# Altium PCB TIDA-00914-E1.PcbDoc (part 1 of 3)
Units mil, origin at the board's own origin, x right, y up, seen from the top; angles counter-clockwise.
Board outline 6575 x 7007.88 mil, 4 copper layers (Top Layer, GND, PWR, Bottom Layer), stack 79.834 mil thick; 302 components, 122 nets, 688 pads, 184 vias.
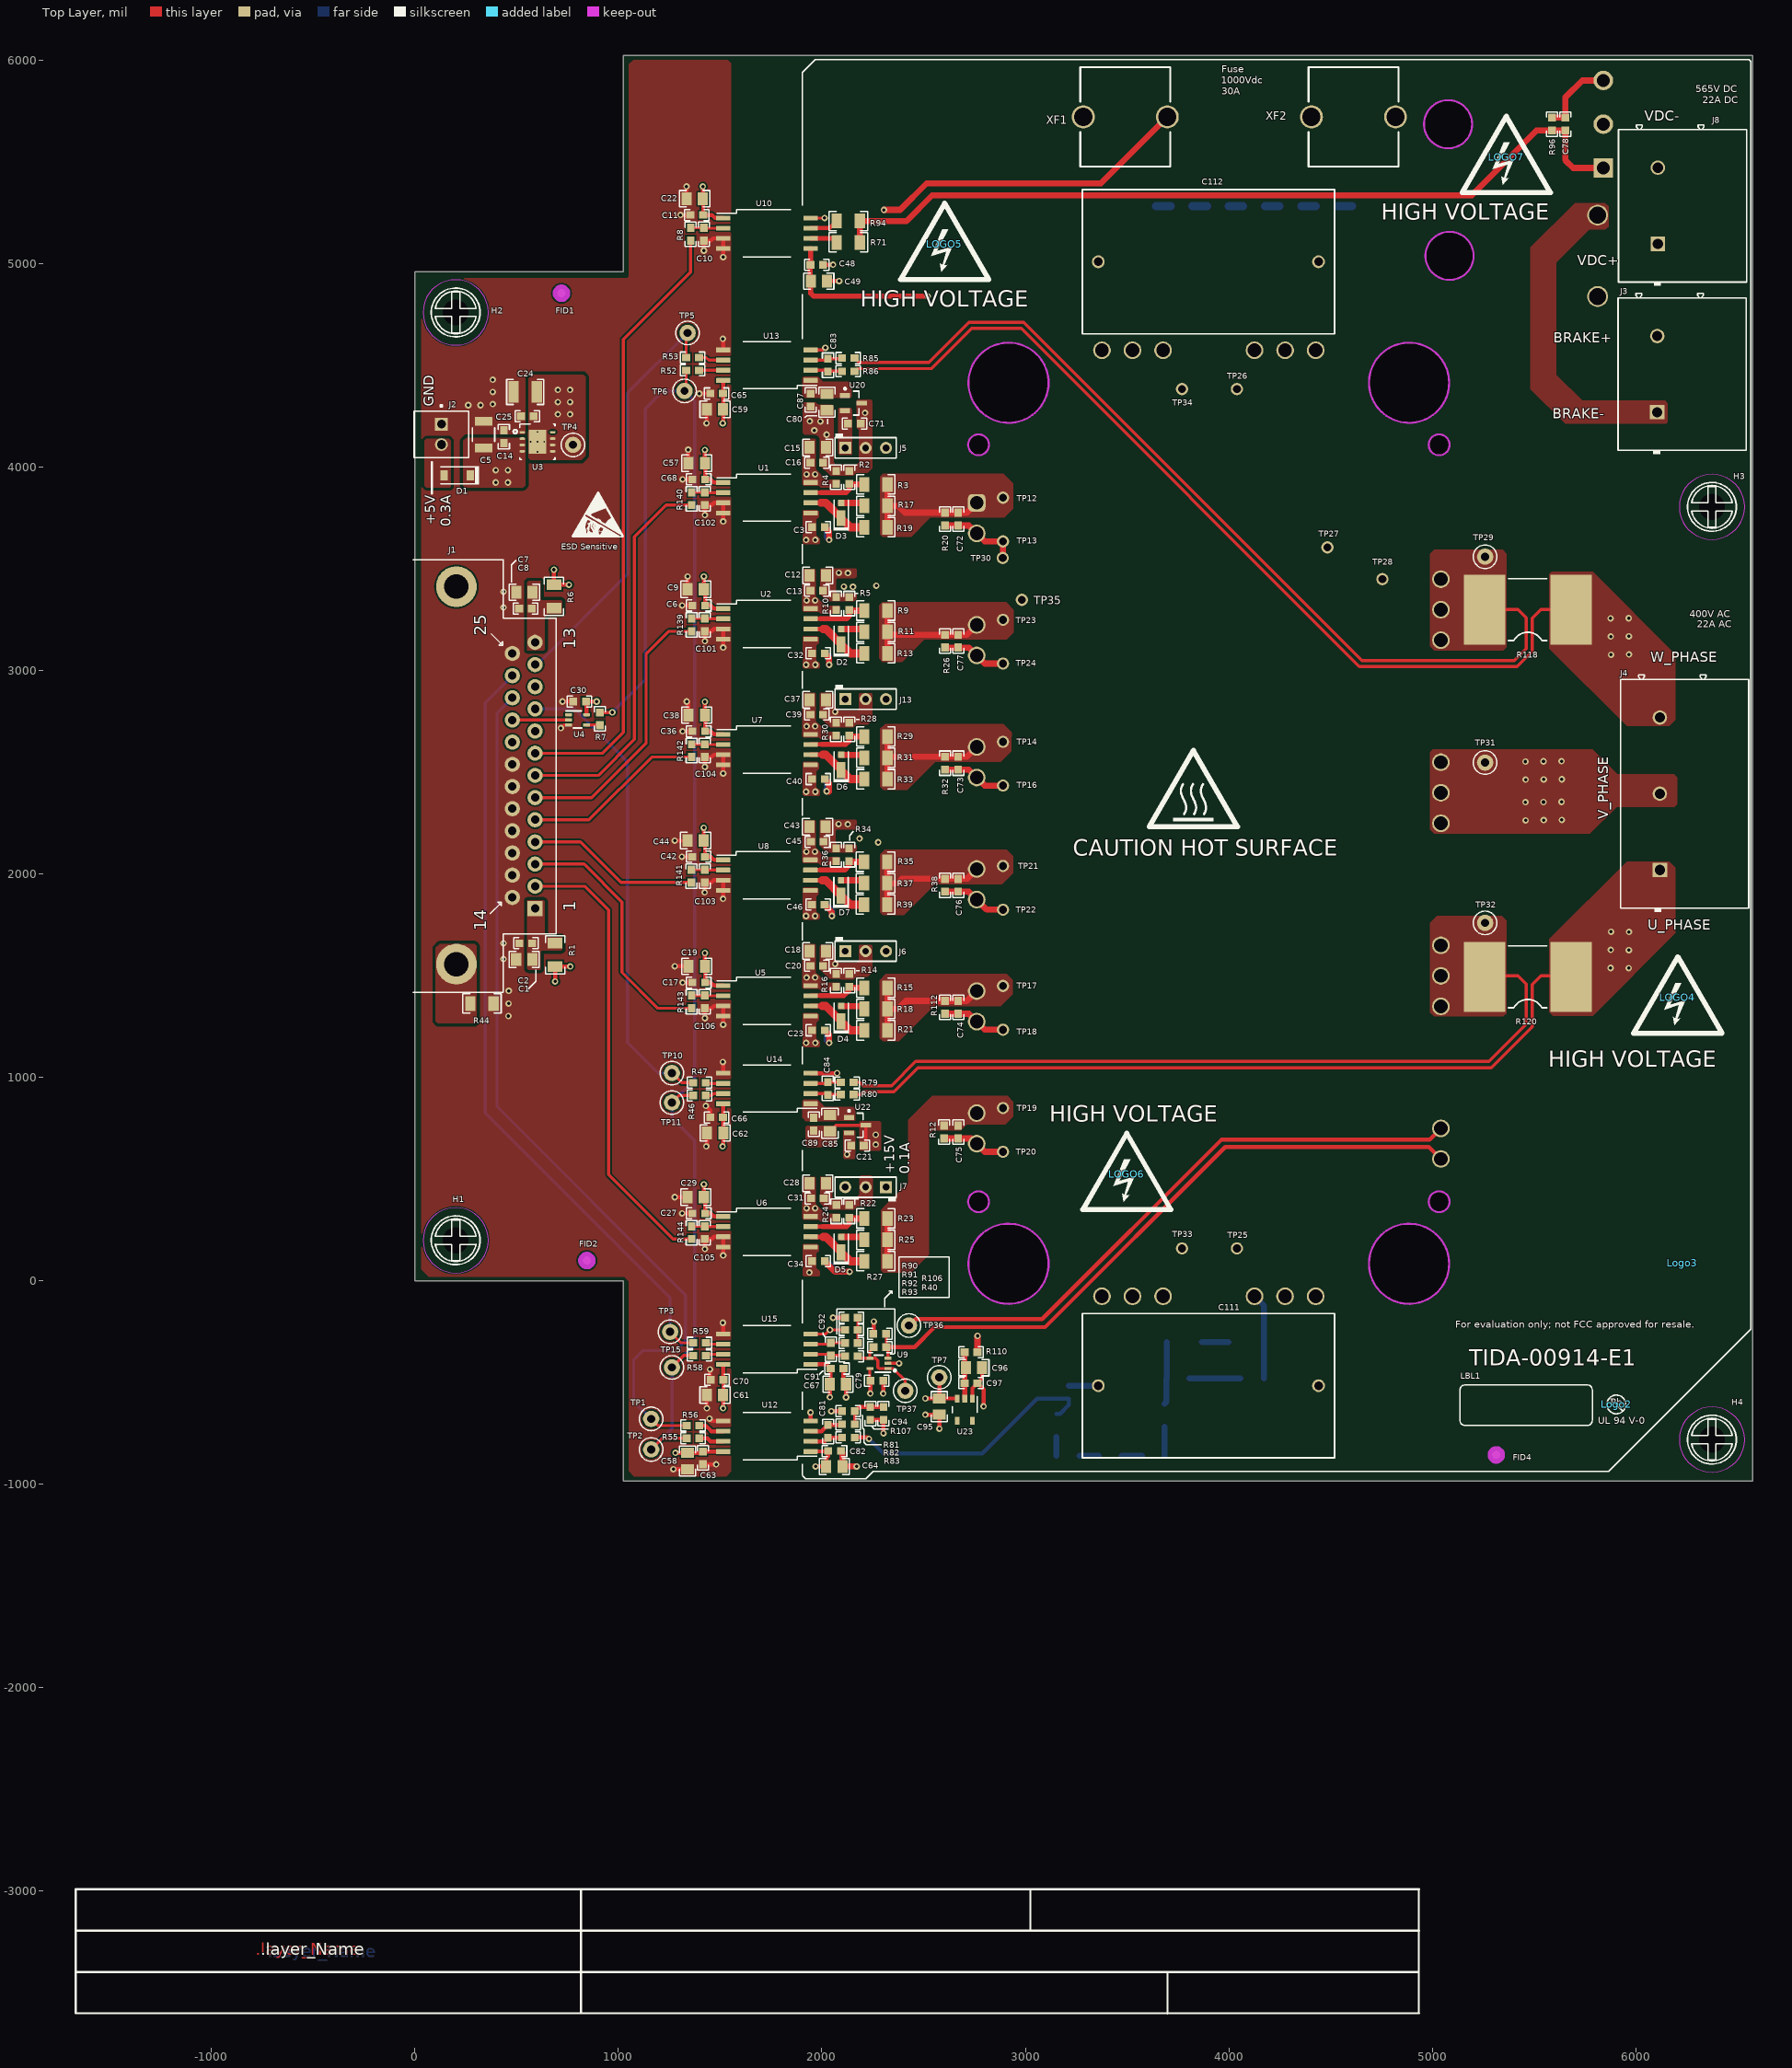
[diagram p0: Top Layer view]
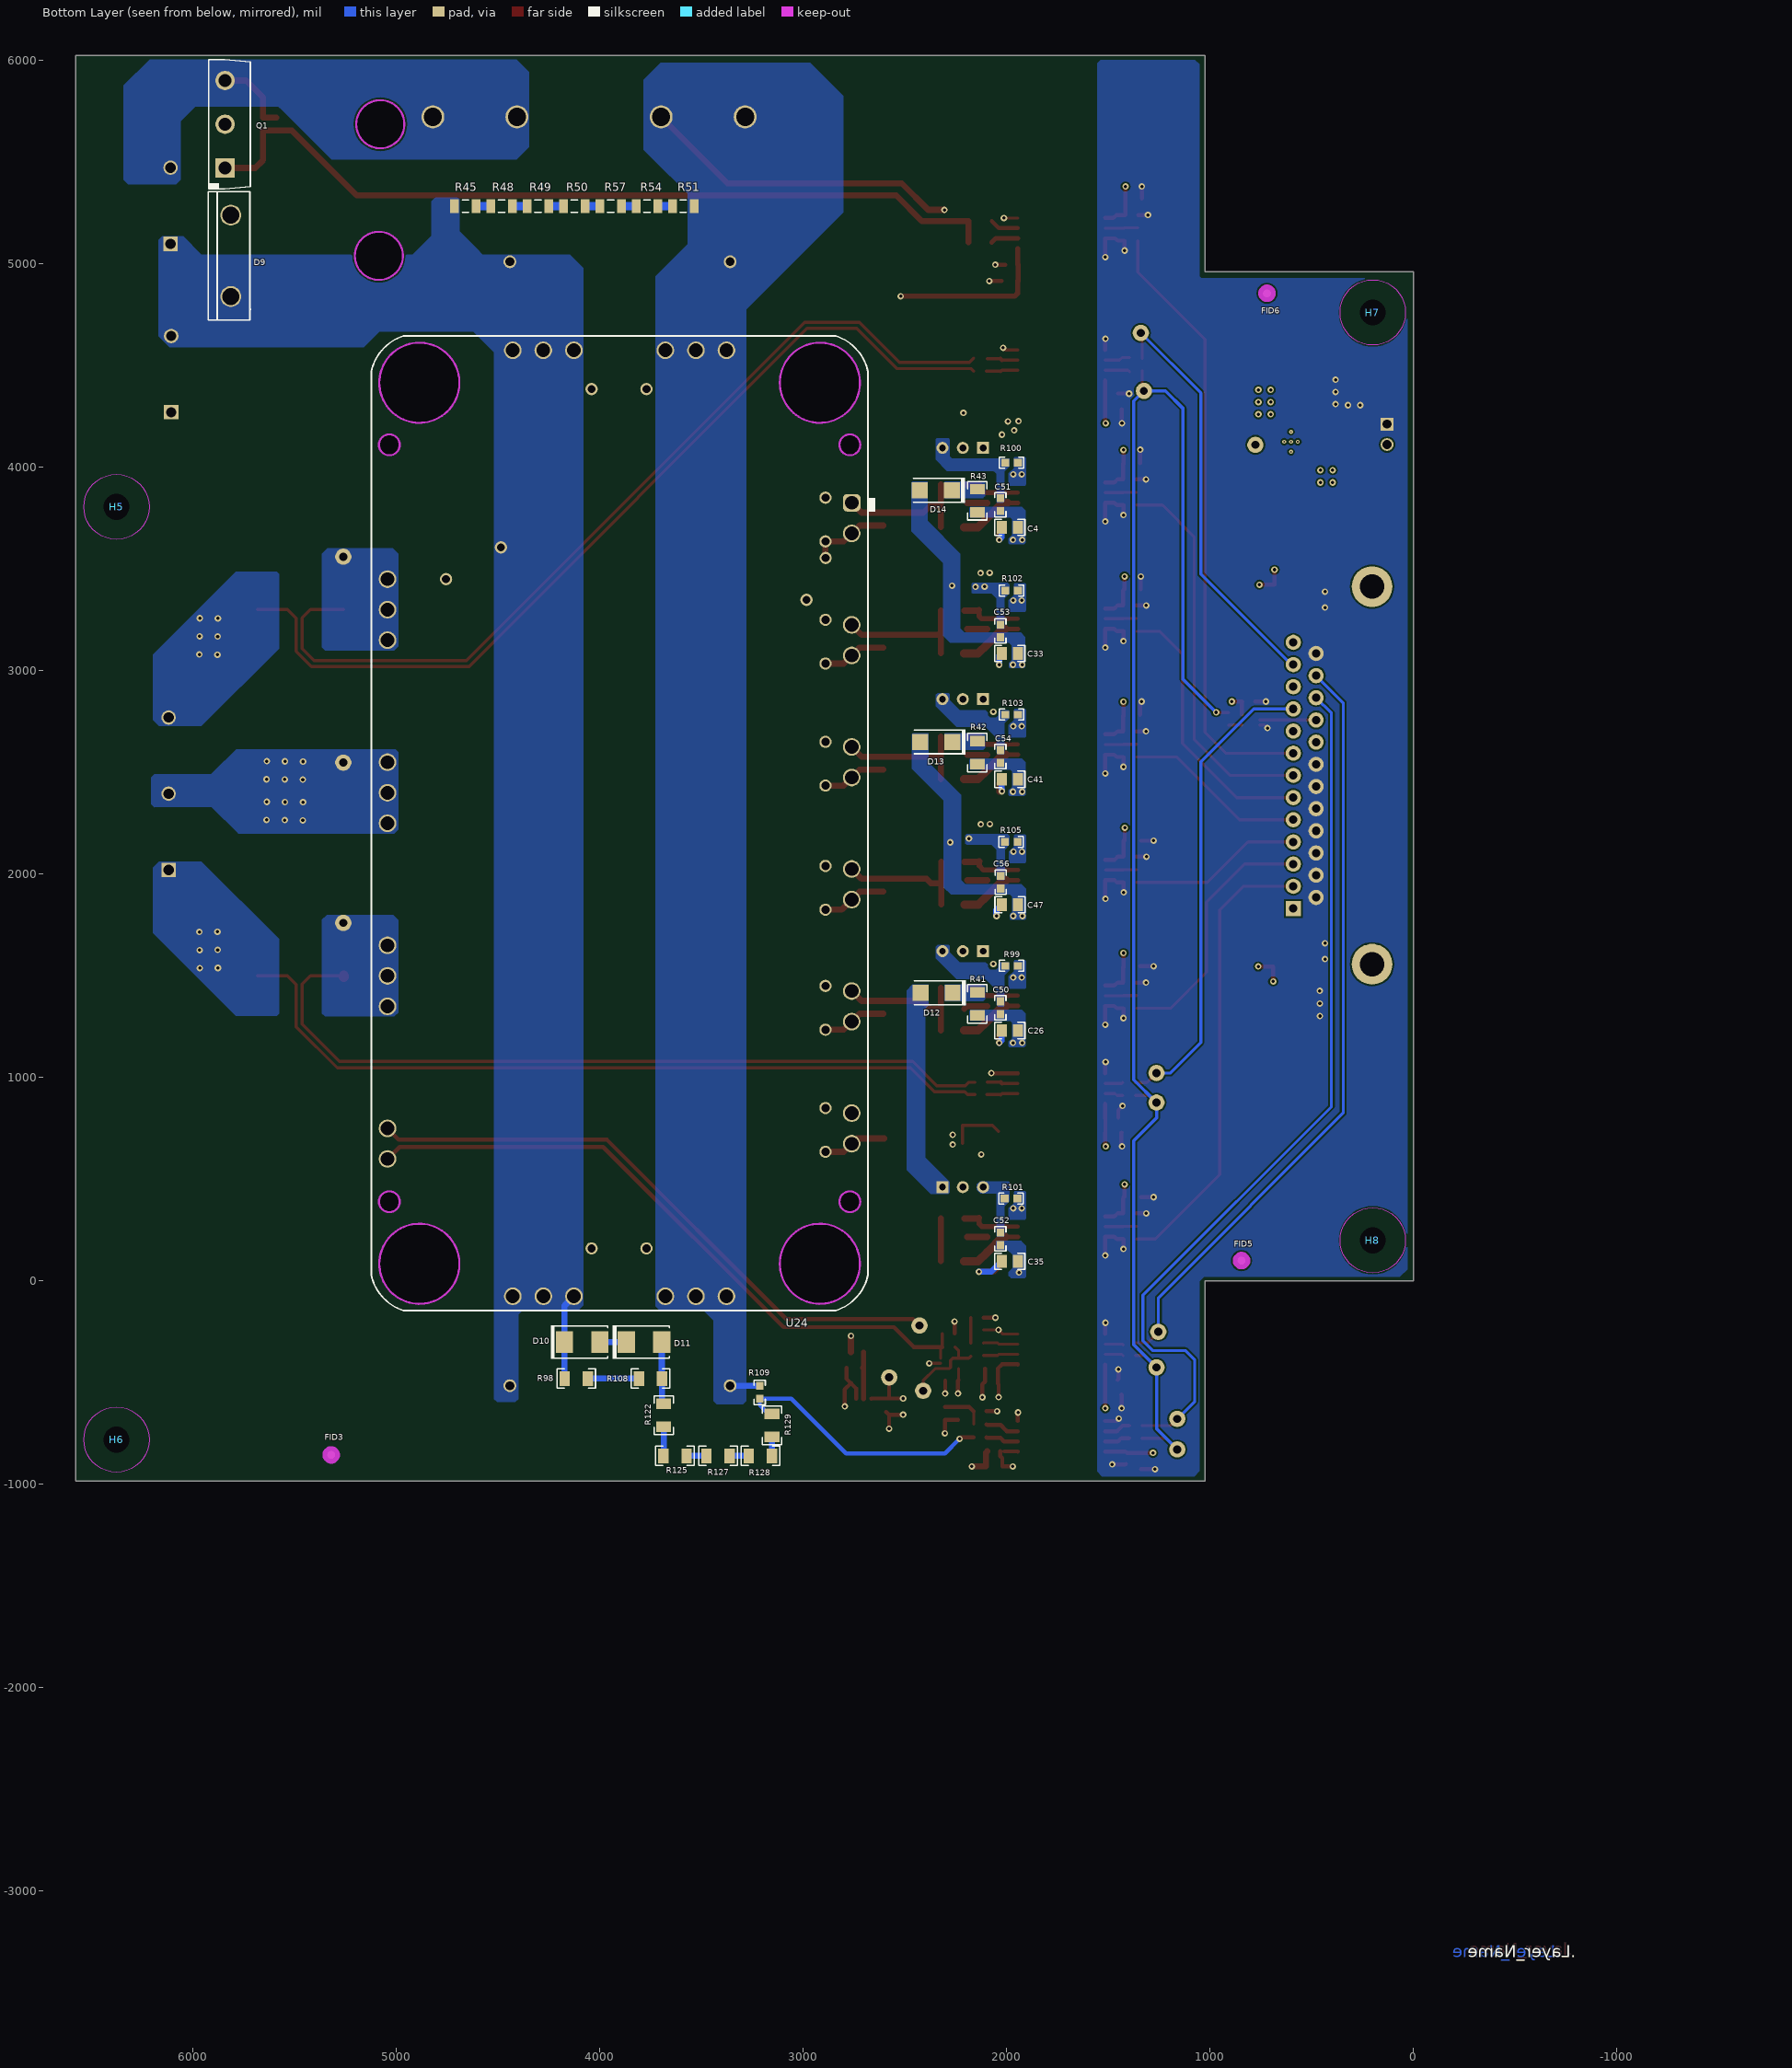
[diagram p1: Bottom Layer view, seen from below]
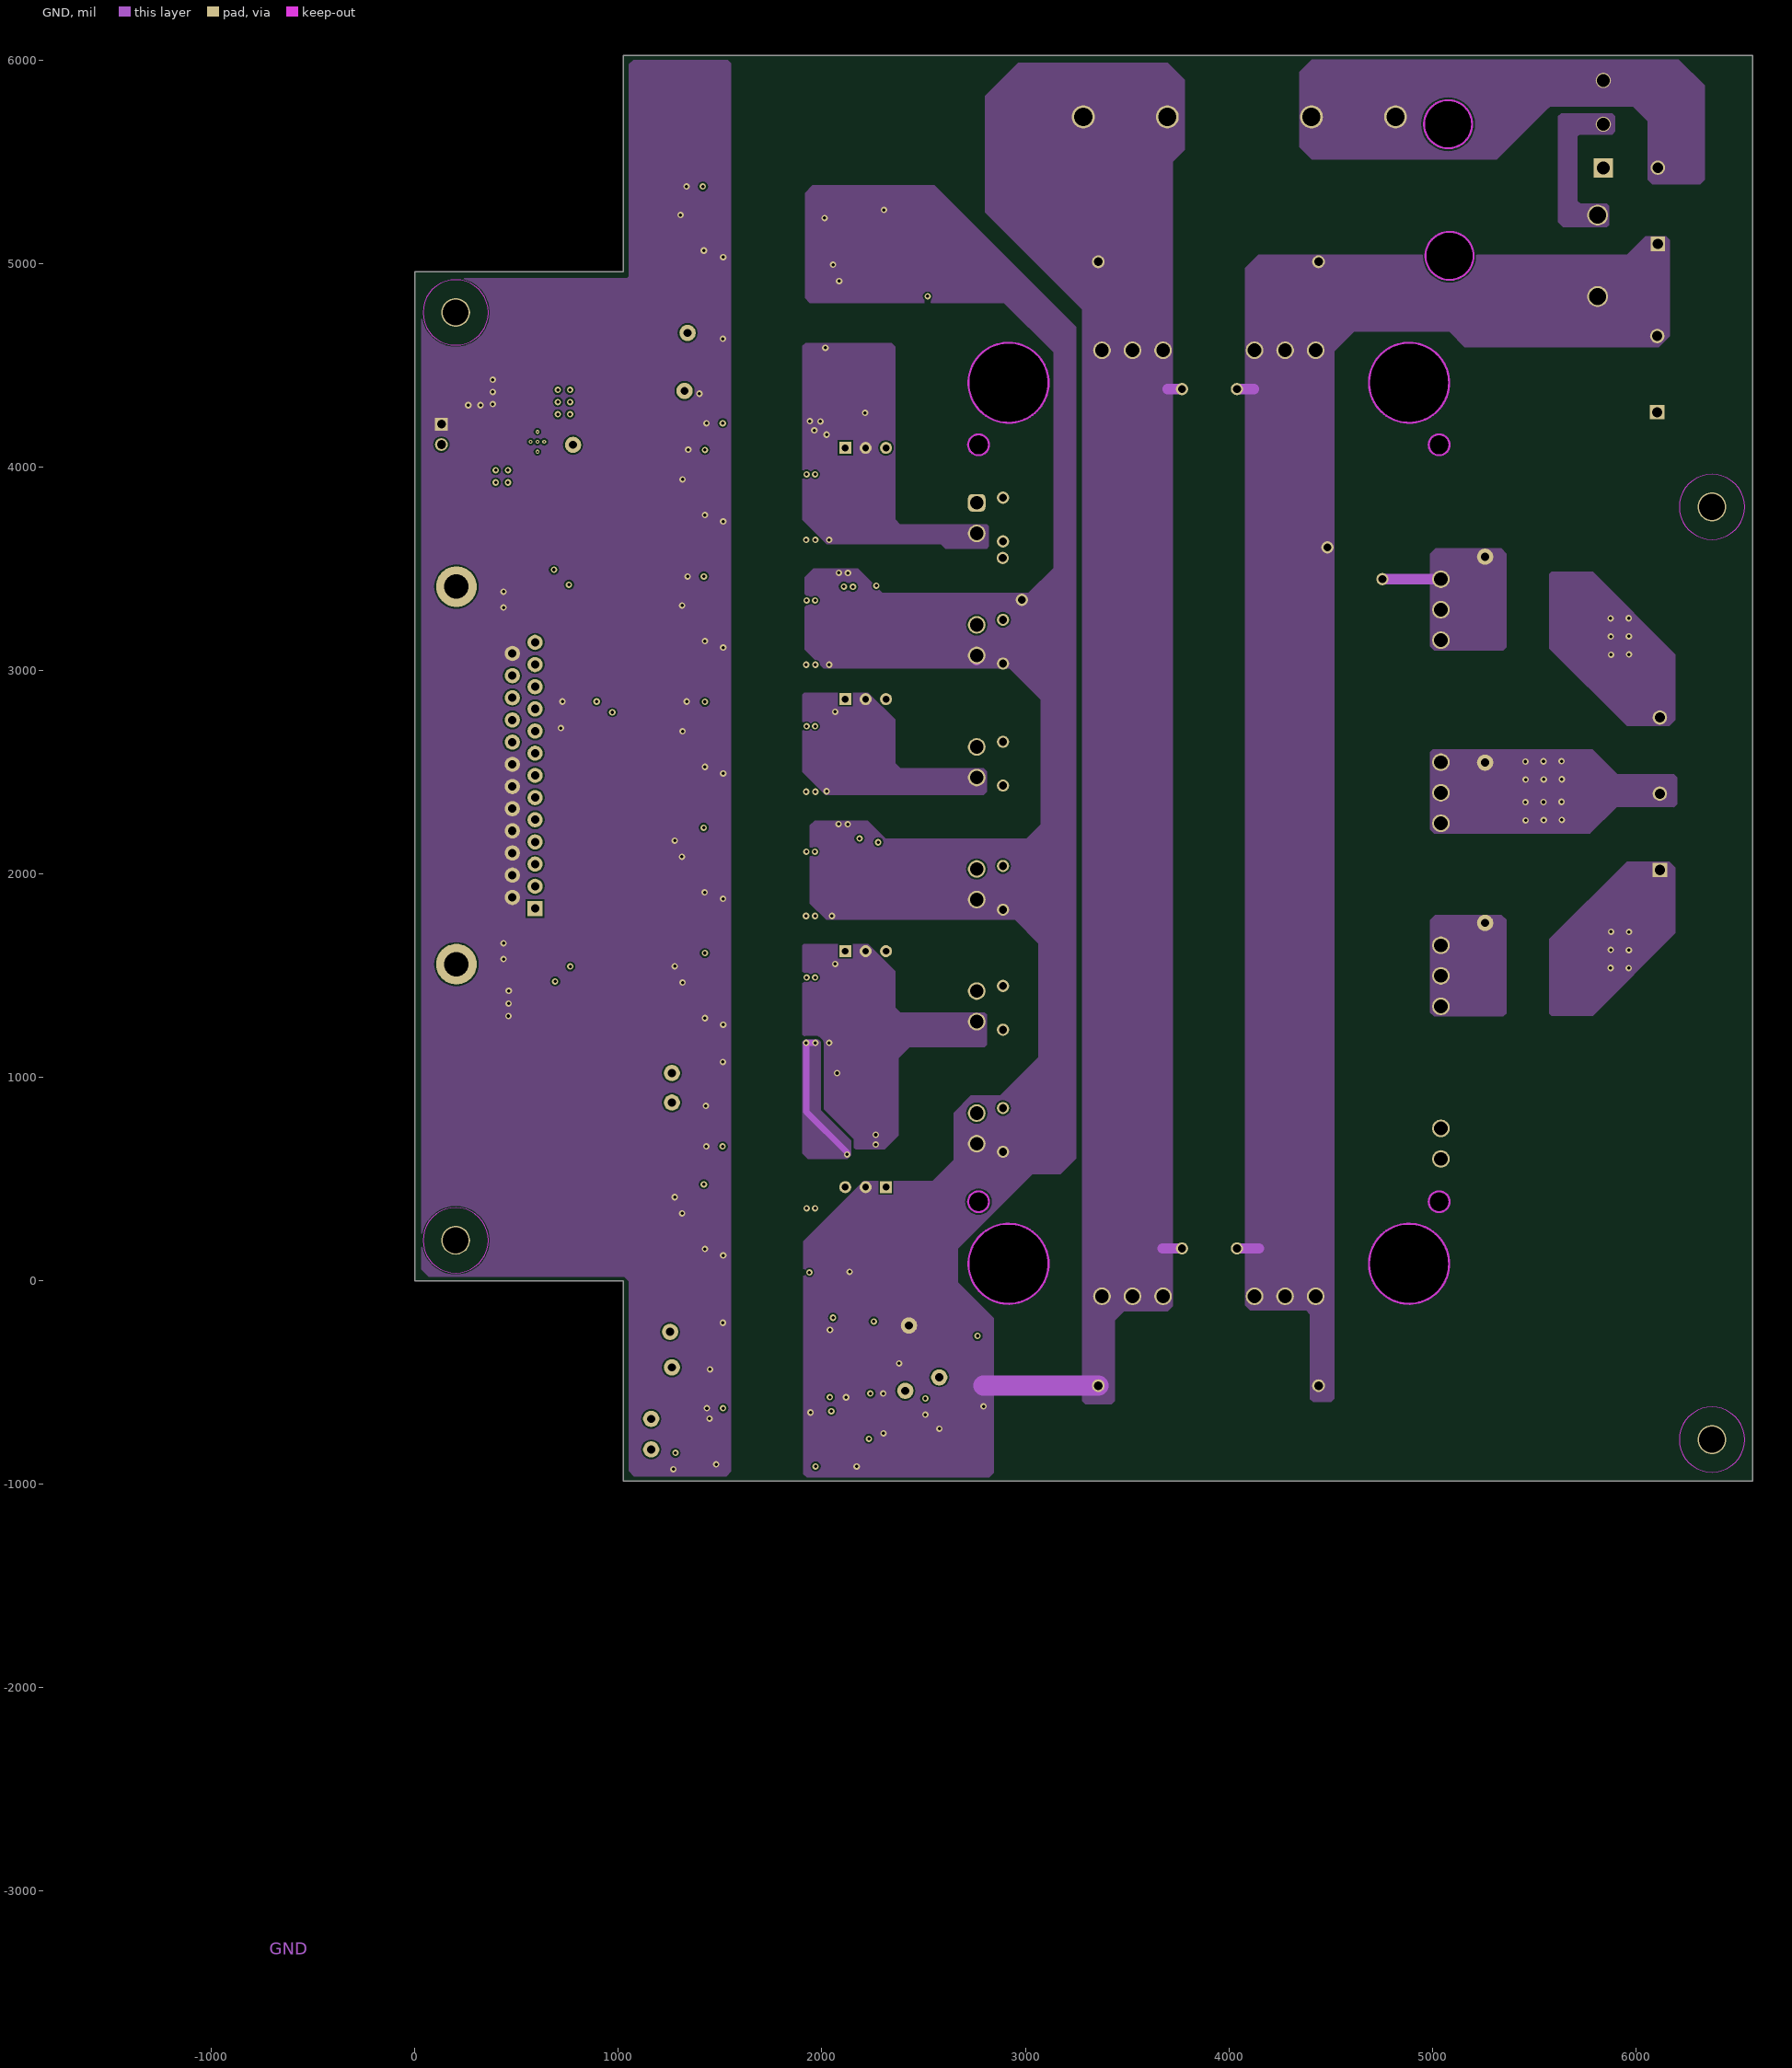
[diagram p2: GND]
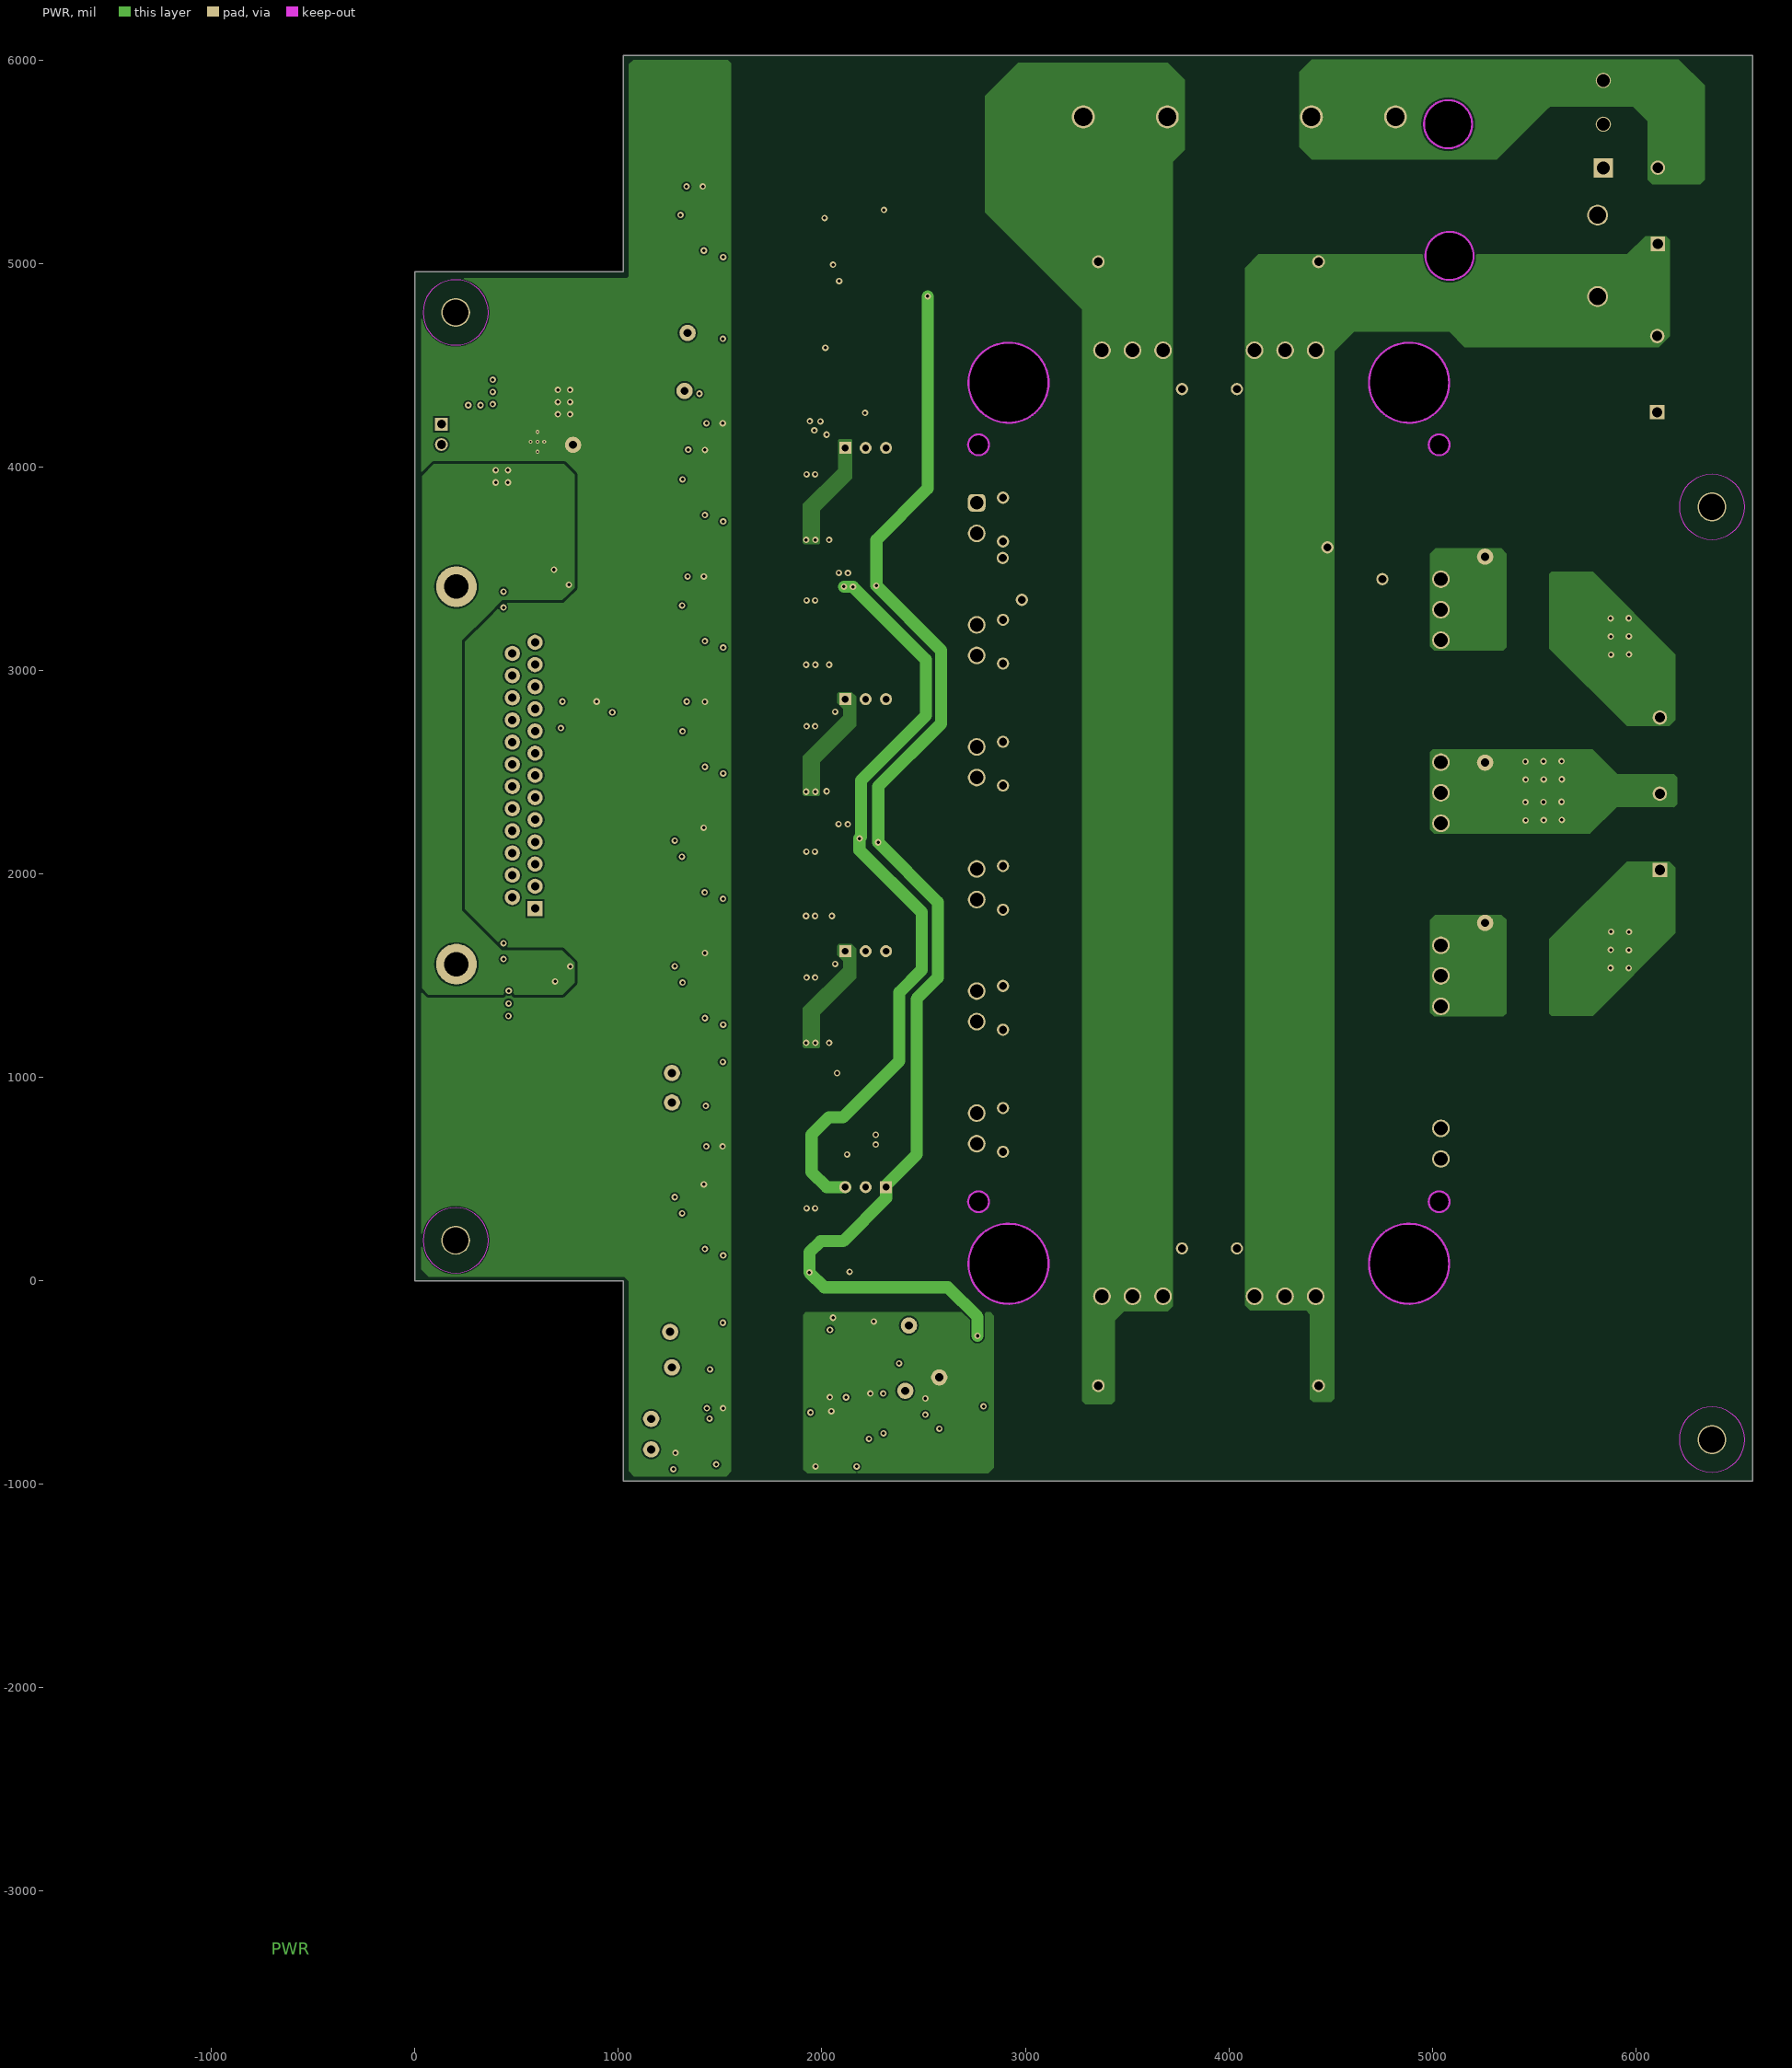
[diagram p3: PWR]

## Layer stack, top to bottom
Top Solder: solder mask 0.4, Solder Resist, Dk 3.5
Top Layer: signal copper 1.4
Dielectric1: core 59.2, FR-4, Dk 4.8
GND: signal copper 1.417
Dielectric 2: prepreg 5, Dk 4.2
PWR: signal copper 1.417
Dielectric 3: core 10, Dk 4.2
Bottom Layer: signal copper 1.4
Bottom Solder: solder mask 0.4, Solder Resist, Dk 3.5

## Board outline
0,0 0,4960.63 1024.73,4960.63 1024.73,6023.62 6575,6023.62 6575,-984.25 1024.73,-984.25 1024.73,0

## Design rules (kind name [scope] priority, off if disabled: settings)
AcuteAngle [All] p1: minimum=4.50000000000000E+0001 checktracksonly=FALSE
AssemblyTestPointUsage [All] p1: valid=2
Clearance "High voltage" [InNetClass('HIGH voltage') vs InNetClass('LOW voltage')] p1: gap=8 ignorepadtopadclearanceinfootprint=FALSE except(0: Arc-Hole Track-Hole SMDPad-Hole THPad-Hole Via-Hole Fill-Hole Poly-Hole Region-Hole Text-Hole; 120: Track-Track Track-Via Track-Poly)
Clearance Clearance_1 [All] p2: gap=8 ignorepadtopadclearanceinfootprint=FALSE except(0: Arc-Hole Track-Hole SMDPad-Hole THPad-Hole Via-Hole Fill-Hole Poly-Hole Region-Hole Text-Hole; 15: Poly-Poly)
Clearance Clearance_Wtop [InNet('W_PHASE_REF') vs InNet('W_PHASE')] p3: gap=0 ignorepadtopadclearanceinfootprint=FALSE except(15: Track-Track)
Clearance Clearance_Vtop [InNet('VDC-') vs InNet('NetR40_1')] p4: gap=0 ignorepadtopadclearanceinfootprint=FALSE except(8: Track-Track)
Clearance Clearance_utop [InNet('U_PHASE_REF') vs InNet('U_PHASE')] p5: gap=0 ignorepadtopadclearanceinfootprint=FALSE except(15: Track-Track)
Clearance Clearance_MTG_COPPER [InPadClass('MTG') vs InPolygon] p6: gap=40 ignorepadtopadclearanceinfootprint=FALSE except(0: Arc-Hole Track-Hole SMDPad-Hole THPad-Hole Via-Hole Fill-Hole Poly-Hole Region-Hole Text-Hole)
Clearance Clearance_Boardedge_poly [OnCopper and InPolygon vs IsKeepOut] p7: gap=20 ignorepadtopadclearanceinfootprint=FALSE except(0: Arc-Hole Track-Hole SMDPad-Hole THPad-Hole Via-Hole Fill-Hole Poly-Hole Region-Hole Text-Hole)
Clearance "Shape to Shape" [InPolygon vs InPolygon] p8: gap=20 ignorepadtopadclearanceinfootprint=FALSE except(0: Arc-Hole Track-Hole SMDPad-Hole THPad-Hole Via-Hole Fill-Hole Poly-Hole Region-Hole Text-Hole)
Clearance "shape to all" [InPolygon] p9: gap=15 ignorepadtopadclearanceinfootprint=FALSE except(0: Arc-Hole Track-Hole SMDPad-Hole THPad-Hole Via-Hole Fill-Hole Poly-Hole Region-Hole Text-Hole)
Clearance "Clearance_via_thr pin" [IsVia vs IsThruPin] p10: gap=8 ignorepadtopadclearanceinfootprint=FALSE except(0: Arc-Hole Track-Hole SMDPad-Hole THPad-Hole Via-Hole Fill-Hole Poly-Hole Region-Hole Text-Hole)
Clearance "SMD to Via" [IsSMTPin vs IsVia] p11: gap=8 ignorepadtopadclearanceinfootprint=FALSE except(0: Arc-Hole Track-Hole SMDPad-Hole THPad-Hole Via-Hole Fill-Hole Poly-Hole Region-Hole Text-Hole)
DiffPairsRouting DiffPair_DiffPairsRouting [InDifferentialPair ('kan')] p1: maxlimit=10 minlimit=10 mostfreqgap=10 toplayer_minwidth=15 toplayer_maxwidth=15 toplayer_prefwidth=15 midlayer1_minwidth=15 midlayer1_maxwidth=15 midlayer1_prefwidth=15 midlayer2_minwidth=15 midlayer2_maxwidth=15 midlayer2_prefwidth=15 bottomlayer_minwidth=15 bottomlayer_maxwidth=15 bottomlayer_prefwidth=15 maxuncoupledlength=500
DiffPairsRouting DiffPair_DiffPairsRouting_1 [InDifferentialPair ('kan')] p2: maxlimit=10 minlimit=10 mostfreqgap=10 toplayer_minwidth=15 toplayer_maxwidth=15 toplayer_prefwidth=15 midlayer1_minwidth=15 midlayer1_maxwidth=15 midlayer1_prefwidth=15 midlayer2_minwidth=15 midlayer2_maxwidth=15 midlayer2_prefwidth=15 bottomlayer_minwidth=15 bottomlayer_maxwidth=15 bottomlayer_prefwidth=15 maxuncoupledlength=500
DiffPairsRouting [All] p3: maxlimit=100 minlimit=10 mostfreqgap=10 toplayer_minwidth=15 toplayer_maxwidth=15 toplayer_prefwidth=15 midlayer1_minwidth=15 midlayer1_maxwidth=15 midlayer1_prefwidth=15 midlayer2_minwidth=15 midlayer2_maxwidth=15 midlayer2_prefwidth=15 bottomlayer_minwidth=15 bottomlayer_maxwidth=15 bottomlayer_prefwidth=15 maxuncoupledlength=1000
FabricationTestPointUsage TestPointUsage [All] p1: valid=2 allowmultiple=FALSE
FabricationTestpoint Testpoint [All] p1: side=3 testpointundercomponent=TRUE minsize=40 maxsize=100 preferedsize=60 minholesize=0 maxholesize=40 preferedholesize=32 testpointgrid=1 allowsidetop=TRUE allowsidebottom=TRUE usegrid=TRUE gridtolerance=0.01
FanoutControl Fanout_LCC [IsLCC] p1: bgadir=Out bgaviamode=Centered fanoutstyle=Auto fanoutdirection=Alternating viagrid=1 // Fanout_LCC (Default Rule)
FanoutControl Fanout_BGA [IsBGA] p2: bgadir=Out bgaviamode=Centered fanoutstyle=Auto fanoutdirection=Alternating viagrid=1 // Fanout_BGA (Default Rule)
FanoutControl Fanout_Default [All] p4: bgadir=Out bgaviamode=Centered fanoutstyle=Auto fanoutdirection=Alternating viagrid=1 // Fanout_Default (Default Rule)
FanoutControl Fanout_Small [(CompPinCount < 5)] p5: bgadir=Out bgaviamode=Centered fanoutstyle=Auto fanoutdirection=OutThenIn viagrid=1 // Fanout_Small (Default Rule)
HoleSize [All] p1: absolutevalues=TRUE maxlimit=1500 minlimit=7 maxpercent=80.000 minpercent=20.000
MatchedLengths DiffPair_MatchedLengths [InDifferentialPair ('kan')] p1: tolerance=1000 checknetsindiffpair=TRUE checkdiffpairvsdiffpair=FALSE checkxsignals=FALSE checkothers=FALSE
MatchedLengths DiffPair_MatchedLengths_1 [InDifferentialPair ('kan')] p2: tolerance=1000 checknetsindiffpair=TRUE checkdiffpairvsdiffpair=FALSE checkxsignals=FALSE checkothers=FALSE
MinimumAnnularRing [All] p1: minimumring=5
MinimumAnnularRing MinimumAnnularRing_ThermalPadVias [IsVia and InAnyComponent] p2: minimumring=5.91
MinimumSolderMaskSliver MinimumSolderMaskSliver_Logo [InComponentClass('Logo') vs InComponentClass('Logo')] p1: minsoldermaskwidth=0.7
MinimumSolderMaskSliver [All] p2: minsoldermaskwidth=3.94
PlaneClearance [All] p1: clearance=15
PlaneConnect [All] p1: planeconnectstyle=Direct reliefexpansion=10 reliefentries=4 reliefconductorwidth=10 reliefairgap=10
PolygonConnect [All] p1: connectstyle=Direct reliefconductorwidth=10 reliefentries=4 polygonreliefangle="90 Angle" airgapwidth=10
RoutingVias RoutingVias_power [InNetClass('POWER')] p1: holewidth=16 width=32 viastyle="Through Hole" minholewidth=7.87 minwidth=19.68 maxholewidth=16 maxwidth=32
RoutingVias ThermalPadVias [IsVia and InAnyComponent] p2: holewidth=8 width=20 viastyle="Through Hole" minholewidth=7.87 minwidth=19 maxholewidth=12 maxwidth=24
RoutingVias [All] p3: holewidth=12 width=24 viastyle="Through Hole" minholewidth=12 minwidth=24 maxholewidth=16 maxwidth=32
SMDToCorner [All] p1: distance=30000
SilkToSilkClearance [All] p1: silktosilkclearance=5
SilkToSolderMaskClearance SilkscreenOverComponentPads [IsPad] p1: minsilkscreentomaskgap=5 clearancetoexposedcopper=TRUE
SolderMaskExpansion [All] p1: expansion=3
Width Width_power [InNetClass('pwr')] p1: maxlimit=200 minlimit=8 preferedwidth=20
Width [All] p2: maxlimit=250 minlimit=10 preferedwidth=20 checkconnectedcopper=TRUE
16 further rules are at their usual default settings.

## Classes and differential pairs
component class "TIDA-00914-E1_Gate drivers": C3 C4 C6 C9 C10 C11 C12 C13 C15 C16 C17 C18 C19 C20 C22 C23 C26 C27 C28 C29 C31 C32 C33 C34 C35 C36 C37 C38 C39 C40 C41 C42 C43 C44 C45 C46 C47 C48 C49 C50 C51 C52 C53 C54 C56 C57 C68 C101 C102 C103 C104 C105 C106 D2 D3 D4 D5 D6 D7 D12 D13 D14 J5 J6 J7 J13 R2 R3 R4 R5 R8 R9 R10 R11 R13 R14 R15 R16 R17 R18 R19 R21 R22 R23 R24 R25 R27 R28 R29 R30 R31 R33 R34 R35 R36 R37 R39 R41 R42 R43 R71 R94 R99 R100 R101 R102 R103 R105 R139 R140 R141 R142 R143 R144 U1 U2 U5 U6 U7 U8 U10
component class "TIDA-00914-E1_IGBT Module, Temp and DC link sense": C58 C61 C63 C64 C67 C70 C72 C73 C74 C75 C76 C77 C78 C79 C81 C82 C91 C92 C94 C95 C96 C97 C111 C112 D9 D10 D11 J3 J4 J8 Q1 R12 R20 R26 R32 R38 R40 R45 R48 R49 R50 R51 R54 R55 R56 R57 R58 R59 R81 R82 R83 R90 R91 R92 R93 R96 R98 R106 R107 R108 R109 R110 R112 R118 R120 R122 R125 R127 R128 R129 TP1 TP2 TP3 TP7 TP12 TP13 TP14 TP15 TP16 TP17 TP18 TP19 TP20 TP21 TP22 TP23 TP24 TP25 TP26 TP27 TP28 TP29 TP30 TP31 TP32 TP33 TP34 TP35 TP36 TP37 U9 U12 U15 U23 U24 XF1 XF2
component class "TIDA-00914-E1_Current sense, MCU Interface": C1 C2 C5 C7 C8 C14 C21 C24 C25 C30 C59 C62 C65 C66 C71 C80 C83 C84 C85 C87 C89 D1 J1 J2 R1 R6 R7 R44 R46 R47 R52 R53 R79 R80 R85 R86 TP4 TP5 TP6 TP10 TP11 U3 U4 U13 U14 U20 U22
component class TIDA-00914-E1_EVM_Hardware: "CAUTION HOT SURFACE" "ESD Sensitive" FID1 FID2 FID3 FID4 FID5 FID6 H1 H2 H3 H4 H5 H6 H7 H8 LBL1 Logo2 Logo3 LOGO4 LOGO5 LOGO6 LOGO7 ZZ1 ZZ2 ZZ3 ZZ4
component class FiducialMark: FID1 FID2 FID3 FID4 FID5 FID6
pad class MTG: H1-1 H2-1 H3-1 H4-1 H5-0 H6-0 H7-0 H8-0
component class Header: J5 J6 J7 J13
component class AssemblyNote: ZZ1 ZZ2 ZZ3 ZZ4
component class Label: LBL1

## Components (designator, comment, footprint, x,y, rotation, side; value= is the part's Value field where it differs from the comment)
C1 "C2012X7R1V475K125AC" 0805_HV 537,1580 r0 top value=4.7uF
C2 "C1608X7R1H104K" 0603 545,1660 r0 top value=0.1uF
C3 "C1608X7R1H474K080AC" 0603 1983,3705 r0 top value=0.47uF
C4 "C2012X7R1V475K125AC" 0805_HV 1984,3704 r0 bottom value=4.7uF
C5 "UMK325AB7106KM-T" 1210_280 337,4160 r90 top value=10uF
C6 "C1608X7R1H104K" 0603 1395,3320 r180 top value=0.1uF
C7 "C2012X7R1V475K125AC" 0805_HV 538,3385 r180 top value=4.7uF
C8 "C1608X7R1H104K" 0603 543,3305 r180 top value=0.1uF
C9 "C2012X7R1V475K125AC" 0805_HV 1380,3400 r180 top value=4.7uF
C10 "GRM1885C1H120JA01D" 0603 1420,5145 r270 top value=12pF
C11 "C1608X7R1H104K" 0603 1385,5240 r180 top value=0.1uF
C12 "C2012X7R1V475K125AC" 0805_HV 1980,3468 r180 top value=4.7uF
C13 "C1608X7R1H474K080AC" 0603 1975,3393 r180 top value=0.47uF
C14 "C1608X7R1H104K" 0603 437,4150 r90 top value=0.1uF
C15 "C2012X7R1V475K125AC" 0805_HV 1980,4097 r180 top value=4.7uF
C16 "C1608X7R1H474K080AC" 0603 1975,4022 r180 top value=0.47uF
C17 "C1608X7R1H104K" 0603 1395,1466.97 r180 top value=0.1uF
C18 "C2012X7R1V475K125AC" 0805_HV 1980,1621.97 r180 top value=4.7uF
C19 "C2012X7R1V475K125AC" 0805_HV 1385,1546.97 r180 top value=4.7uF
C20 "C1608X7R1H474K080AC" 0603 1975,1548.97 r180 top value=0.47uF
C21 "C1608X7R1H104K" 0603 2174.77,665.55 r180 top value=0.1uF
C22 "C2012X7R1V475K125AC" 0805_HV 1375,5320 r180 top value=4.7uF
C23 "C1608X7R1H474K080AC" 0603 1983,1231.97 r0 top value=0.47uF
C24 "C1210C107M4PAC7800" 1210_270 542,4370 r180 top value=100uF
C25 "C1608X7R1H104K" 0603 552,4250 r180 top value=0.1uF
C26 "C2012X7R1V475K125AC" 0805_HV 1984,1230.97 r0 bottom value=4.7uF
C27 "C1608X7R1H104K" 0603 1395,332 r180 top value=0.1uF
C28 "C2012X7R1V475K125AC" 0805_HV 1980,480 r180 top value=4.7uF
C29 "C2012X7R1V475K125AC" 0805_HV 1380,412 r180 top value=4.7uF
C30 "C1608X7R1H104K" 0603 809,2848 r180 top value=0.1uF
C31 "C1608X7R1H474K080AC" 0603 1978,406 r180 top value=0.47uF
C32 "C1608X7R1H474K080AC" 0603 1983,3085 r0 top value=0.47uF
C33 "C2012X7R1V475K125AC" 0805_HV 1984,3085 r0 bottom value=4.7uF
C34 "C1608X7R1H474K080AC" 0603 1983,97 r0 top value=0.47uF
C35 "C2012X7R1V475K125AC" 0805_HV 1984,97 r0 bottom value=4.7uF
C36 "C1608X7R1H104K" 0603 1395,2701.97 r180 top value=0.1uF
C37 "C2012X7R1V475K125AC" 0805_HV 1980,2856.97 r180 top value=4.7uF
C38 "C2012X7R1V475K125AC" 0805_HV 1385,2781.97 r180 top value=4.7uF
C39 "C1608X7R1H474K080AC" 0603 1975,2783.97 r180 top value=0.47uF
C40 "C1608X7R1H474K080AC" 0603 1983,2466.97 r0 top value=0.47uF
C41 "C2012X7R1V475K125AC" 0805_HV 1984,2465.97 r0 bottom value=4.7uF
C42 "C1608X7R1H104K" 0603 1394,2085 r180 top value=0.1uF
C43 "C2012X7R1V475K125AC" 0805_HV 1979,2233 r180 top value=4.7uF
C44 "C2012X7R1V475K125AC" 0805_HV 1379,2165 r180 top value=4.7uF
C45 "C1608X7R1H474K080AC" 0603 1977,2159 r180 top value=0.47uF
C46 "C1608X7R1H474K080AC" 0603 1982,1850 r0 top value=0.47uF
C47 "C2012X7R1V475K125AC" 0805_HV 1983,1850 r0 bottom value=4.7uF
C48 "C1608X7R1H474K080AC" 0603 1975,4995 r0 top value=0.47uF
C49 "C2012X7R1V475K125AC" 0805_HV 1985,4915 r0 top value=4.7uF
C50 "C1608X7R1H474K080AC" 0603 2030,1342.97 r90 bottom value=0.47uF
C51 "C1608X7R1H474K080AC" 0603 2030,3816 r90 bottom value=0.47uF
C52 "C1608X7R1H474K080AC" 0603 2030,207 r90 bottom value=0.47uF
C53 "C1608X7R1H474K080AC" 0603 2030,3195 r90 bottom value=0.47uF
C54 "C1608X7R1H474K080AC" 0603 2030,2577.97 r90 bottom value=0.47uF
C56 "C1608X7R1H474K080AC" 0603 2029,1960 r90 bottom value=0.47uF
C57 "C2012X7R1V475K125AC" 0805_HV 1385,4020 r180 top value=4.7uF
C58 "C2012X7R1V475K125AC" 0805_HV 1340,-885 r90 top value=4.7uF
C59 "C2012X7R1V475K125AC" 0805_HV 1474.73,4284.45 r0 top value=4.7uF
C61 "C2012X7R1V475K125AC" 0805_HV 1474.73,-560.55 r0 top value=4.7uF
C62 "C2012X7R1V475K125AC" 0805_HV 1475.5,728 r0 top value=4.7uF
C63 "C1608X7R1H104K" 0603 1415,-870 r90 top value=0.1uF
C64 "C2012X7R1V475K125AC" 0805_HV 2061,-912 r180 top value=4.7uF
C65 "C1608X7R1H104K" 0603 1482.73,4362.45 r0 top value=0.1uF
C66 "C1608X7R1H104K" 0603 1482.5,804 r0 top value=0.1uF
C67 "C2012X7R1V475K125AC" 0805_HV 2079,-508 r180 top value=4.7uF
C68 "C1608X7R1H104K" 0603 1395,3940 r180 top value=0.1uF
C70 "C1608X7R1H104K" 0603 1484.73,-485.55 r0 top value=0.1uF
C71 "C1608X7R1H104K" 0603 2160,4215 r180 top value=0.1uF
C72 "CGA3E2C0G1H103J080AA" 0603 2670,3745 r270 top value=0.01uF
C73 "CGA3E2C0G1H103J080AA" 0603 2670,2545 r270 top value=0.01uF
C74 "CGA3E2C0G1H103J080AA" 0603 2670,1345 r270 top value=0.01uF
C75 "CGA3E2C0G1H103J080AA" 0603 2670,732 r270 top value=0.01uF
C76 "CGA3E2C0G1H103J080AA" 0603 2670,1945 r270 top value=0.01uF
C77 "CGA3E2C0G1H103J080AA" 0603 2670,3145 r270 top value=0.01uF
C78 "CGA3E2C0G1H103J080AA" 0603 5654,5686.5 r90 top value=0.01uF
C79 "C1608X7R1H104K" 0603 2270,-490 r0 top value=0.1uF
C80 "C2012X7R1V475K125AC" 0805_HV 2025,4320 r90 top value=4.7uF
C81 "GRM1885C1H470JA01D" 0603 2030,-739.5 r90 top value=47pF
C82 "C1608X7R1H104K" 0603 2062.27,-835.95 r180 top value=0.1uF
C83 "GRM1885C1H470JA01D" 0603 2029.73,4501.58 r90 top value=47pF
C84 "GRM1885C1H470JA01D" 0603 2029.5,946 r90 top value=47pF
C85 "C2012X7R1V475K125AC" 0805_HV 2039.77,775.55 r90 top value=4.7uF
C87 "C1608X7R1H104K" 0603 1945,4330 r90 top value=0.1uF
C89 "C1608X7R1H104K" 0603 1959.77,770.55 r90 top value=0.1uF
C91 "C1608X7R1H104K" 0603 2074.73,-430.55 r180 top value=0.1uF
C92 "GRM1885C1H470JA01D" 0603 2044.73,-335.55 r90 top value=47pF
C94 "C1608X7R1H104K" 0603 2303,-651.5 r90 top value=0.1uF
C95 "C2012X7R1V475K125AC" 0805_HV 2577.33,-617.68 r270 top value=4.7uF
C96 "C2012X7R1V475K125AC" 0805_HV 2747.33,-426.68 r0 top value=4.7uF
C97 "C1608X7R1H104K" 0603 2733.33,-502.68 r0 top value=0.1uF
C101 "GRM1885C1H120JA01D" 0603 1425,3225 r270 top value=12pF
C102 "GRM1885C1H120JA01D" 0603 1425,3845 r270 top value=12pF
C103 "GRM1885C1H120JA01D" 0603 1424,1990 r270 top value=12pF
C104 "GRM1885C1H120JA01D" 0603 1425,2606.97 r270 top value=12pF
C105 "GRM1885C1H120JA01D" 0603 1425,237 r270 top value=12pF
C106 "GRM1885C1H120JA01D" 0603 1425,1371.97 r270 top value=12pF
C111 "B32774D1305K000" B32774_3150x1800x2750 3900,-515 r180 top value=3uF
C112 "B32774D1305K000" B32774_3150x1800x2750 3900,5010 r180 top locked value=3uF
"CAUTION HOT SURFACE" "CAUTION HOT SURFACE" IEC_HotSurface_Medium 3826,2420 r0 top
D1 "B0530W-7-F" SOD-123 207,3960 r180 top value=30V
D2 "MSS2P3-M3/89A" MicroSMP 2095,3155 r90 top value=30V
D3 "MSS2P3-M3/89A" MicroSMP 2095,3775 r90 top value=30V
D4 "MSS2P3-M3/89A" MicroSMP 2095,1301.97 r90 top value=30V
D5 "MSS2P3-M3/89A" MicroSMP 2095,167 r90 top value=30V
D6 "MSS2P3-M3/89A" MicroSMP 2095,2536.97 r90 top value=30V
D7 "MSS2P3-M3/89A" MicroSMP 2094,1920 r90 top value=30V
D9 "RHRG30120" TO-247-2 5821.27,5039 r90 bottom value=1200V
D10 "1SMB5956BT3G" SMB 4085.74,-300.55 r180 bottom value=200V
D11 "1SMB5956BT3G" SMB 3781.74,-300.55 r180 bottom value=200V
D12 "BYG23T-M3/TR" SMA 2344,1417 r0 bottom value=1300V
D13 "BYG23T-M3/TR" SMA 2345,2650 r0 bottom value=1300V
D14 "BYG23T-M3/TR" SMA 2348,3887 r0 bottom value=1300V
"ESD Sensitive" "ESD Susceptible" ESD_Overlay_Medium 899,3767 r0 top
FID1 "Fiducial" Fiducial10-20 720,4855 r270 top
FID2 "Fiducial" Fiducial10-20 845,100 r90 top
FID3 "Fiducial" Fiducial10-20 5319.53,-855 r90 bottom
FID4 "Fiducial" Fiducial10-20 5315,-855 r90 top
FID5 "Fiducial" Fiducial10-20 845,100 r90 bottom
FID6 "Fiducial" Fiducial10-20 720,4855 r270 bottom
H1 "MH 3.2mm" MH3.2_H5_W6_KO8_STARHEAD 200,200 r180 top locked
H2 "MH 3.2mm" MH3.2_H5_W6_KO8_STARHEAD 200,4760.63 r180 top locked
H3 "MH 3.2mm" MH3.2_H5_W6_KO8_STARHEAD 6375,3805 r180 top
H4 "MH 3.2mm" MH3.2_H5_W6_KO8_STARHEAD 6375,-780 r180 top
H5 "1902C" Keystone_1902C 6375,3805 r0 bottom
H6 "1902C" Keystone_1902C 6375,-780 r0 bottom
H7 "1902C" Keystone_1902C 200,4760.63 r0 bottom
H8 "1902C" Keystone_1902C 200,200 r0 bottom
J1 "5747461-1" Amp_DB25 397,2485 r90 top locked
J2 "282834-2" TEC_282834-2 129.73,4161.45 r270 top
J3 "1902547" Phoenix_1902547 6228.05,4457.6 r90 top
J4 "1904150" Phoenix_1904150 6241.05,2395 r90 top
J5 "800-10-003-10-001000" Mill-Max_800-10-003-10-001000 2215,4095 r0 top
J6 "800-10-003-10-001000" Mill-Max_800-10-003-10-001000 2215,1621 r0 top
J7 "800-10-003-10-001000" Mill-Max_800-10-003-10-001000 2215,461 r180 top
J8 "1902547" Phoenix_1902547 6231,5285 r90 top
J13 "800-10-003-10-001000" Mill-Max_800-10-003-10-001000 2215,2860 r0 top
LBL1 "Size: 0.65\" x 0.20 \"" Label_650x200 5462,-611 r0 top
Logo2 "Pb-Free Symbol" Pb-Free_Overlay_Small 5905,-607 r0 top
Logo3 "FCC disclaimer" FCC_disclaimer 6228,88 r0 top
LOGO4 "HIGH VOLTAGE" IEC_HighVoltage_medium 6207,1393 r0 top
LOGO5 "HIGH VOLTAGE" IEC_HighVoltage_medium 2604,5097 r0 top
LOGO6 "HIGH VOLTAGE" IEC_HighVoltage_medium 3499,526 r0 top
LOGO7 "HIGH VOLTAGE" IEC_HighVoltage_medium 5364,5525 r0 top
Q1 "NGTB25N120IHLWG" TO-247 5841,5686 r90 bottom value="1200 V"
R1 "CRCW12060000Z0EA" 1206 689,1603 r90 top value=0
R2 "CRCW06030000Z0EA" 0603 2135,3950 r90 top value=0
R3 "CRCW12060000Z0EA" 1206 2265,3915 r0 top value=0
R4 "CRCW06030000Z0EA" 0603 2070,3950 r90 top value=0
R5 "CRCW06030000Z0EA" 0603 2135,3330 r90 top value=0
R6 "CRCW12060000Z0EA" 1206 683,3365 r270 top value=0
R7 "CRCW060322R0JNEA" 0603 909,2763 r90 top value=22
R8 "CRCW06031K00FKEA" 0603 1355,5145 r270 top value=1.00k
R9 "CRCW12060000Z0EA" 1206 2265,3295 r0 top value=0
R10 "CRCW06030000Z0EA" 0603 2070,3330 r90 top value=0
R11 "RC1206FR-0712RL" 1206 2265,3190 r0 top value=12.0
R12 "CRCW060310K0JNEA" 0603 2601,732 r90 top value=10k
R13 "RC1206FR-0712RL" 1206 2265,3085 r0 top value=12.0
R14 "CRCW06030000Z0EA" 0603 2135,1476.97 r90 top value=0
R15 "CRCW12060000Z0EA" 1206 2265,1440.97 r0 top value=0
R16 "CRCW06030000Z0EA" 0603 2070,1476.97 r90 top value=0
R17 "RC1206FR-0712RL" 1206 2265,3810 r0 top value=12.0
R18 "RC1206FR-0712RL" 1206 2265,1336.97 r0 top value=12.0
R19 "RC1206FR-0712RL" 1206 2265,3705 r0 top value=12.0
R20 "CRCW060310K0JNEA" 0603 2605,3745 r90 top value=10k
R21 "RC1206FR-0712RL" 1206 2265,1231.97 r0 top value=12.0
R22 "CRCW06030000Z0EA" 0603 2135,342 r90 top value=0
R23 "CRCW12060000Z0EA" 1206 2265,307 r0 top value=0
R24 "CRCW06030000Z0EA" 0603 2071,342 r90 top value=0
R25 "RC1206FR-0712RL" 1206 2265,202 r0 top value=12.0
R26 "CRCW060310K0JNEA" 0603 2605,3145 r90 top value=10k
R27 "RC1206FR-0712RL" 1206 2265,97 r0 top value=12.0
R28 "CRCW06030000Z0EA" 0603 2135,2711.97 r90 top value=0
R29 "CRCW12060000Z0EA" 1206 2265,2675.97 r0 top value=0
R30 "CRCW06030000Z0EA" 0603 2070,2711.97 r90 top value=0
R31 "RC1206FR-0712RL" 1206 2265,2571.97 r0 top value=12.0
R32 "CRCW060310K0JNEA" 0603 2605,2545 r90 top value=10k
R33 "RC1206FR-0712RL" 1206 2265,2466.97 r0 top value=12.0
R34 "CRCW06030000Z0EA" 0603 2134,2095 r90 top value=0
R35 "CRCW12060000Z0EA" 1206 2264,2060 r0 top value=0
R36 "CRCW06030000Z0EA" 0603 2070,2095 r90 top value=0
R37 "RC1206FR-0712RL" 1206 2264,1955 r0 top value=12.0
R38 "CRCW060310K0JNEA" 0603 2605,1945 r90 top value=10k
R39 "RC1206FR-0712RL" 1206 2264,1850 r0 top value=12.0
R40 "CRCW06030000Z0EA" 0603 2285,-325 r180 top value=0
R41 "CRCW12061R00FKEA" 1206 2143.37,1361.97 r90 bottom value=1.00
R42 "CRCW12061R00FKEA" 1206 2143.37,2596.97 r90 bottom value=1.00
R43 "CRCW12061R00FKEA" 1206 2143.37,3835 r90 bottom value=1.00
R44 "CRCW12060000Z0EA" 1206 329,1364 r180 top value=0
R45 "CRCW1206100KJNEAHP" 1206L 4660,5283.69 r180 bottom value=100k
R46 "CRCW060322R0JNEA" 0603 1397.95,911.55 r180 top value=22
R47 "CRCW060322R0JNEA" 0603 1397.95,974.55 r180 top value=22
R48 "CRCW1206100KJNEAHP" 1206L 4481.5,5283.69 r180 bottom value=100k
R49 "CRCW1206100KJNEAHP" 1206L 4303,5283.69 r180 bottom value=100k
R50 "CRCW1206100KJNEAHP" 1206L 4124.5,5283.69 r180 bottom value=100k
R51 "CRCW1206100KJNEAHP" 1206L 3589,5283.69 r0 bottom value=100k
R52 "CRCW060322R0JNEA" 0603 1364.5,4476 r180 top value=22
R53 "CRCW060322R0JNEA" 0603 1364.5,4539 r180 top value=22
R54 "CRCW1206100KJNEAHP" 1206L 3767.5,5283.69 r0 bottom value=100k
R55 "CRCW060322R0JNEA" 0603 1366.5,-773 r180 top value=22
R56 "CRCW060322R0JNEA" 0603 1366.5,-711 r180 top value=22
R57 "CRCW1206100KJNEAHP" 1206L 3946,5283.69 r0 bottom value=100k
R58 "CRCW060322R0JNEA" 0603 1398.5,-367 r180 top value=22
R59 "CRCW060322R0JNEA" 0603 1398.5,-304 r180 top value=22
R71 "CRCW120616R5FKEA" 1206 2130,5105 r0 top value=16.5
R79 "CRCW06030000Z0EA" 0603 2124.5,976 r180 top value=0
R80 "CRCW06030000Z0EA" 0603 2124.5,916 r180 top value=0
R81 "CRCW060312K1FKEA" 0603 2130,-639.5 r0 top value=12.1k
R82 "CRCW06030000Z0EA" 0603 2130,-704.5 r180 top value=0
R83 "CRCW06030000Z0EA" 0603 2130,-769.5 r180 top value=0
R85 "CRCW06030000Z0EA" 0603 2129.73,4536.58 r180 top value=0
R86 "CRCW06030000Z0EA" 0603 2129.73,4471.58 r180 top value=0
R90 "CRCW06031K00FKEA" 0603 2144.73,-180.55 r180 top value=1.00k
R91 "CRCW06030000Z0EA" 0603 2144.73,-240.55 r0 top value=0
R92 "CRCW06030000Z0EA" 0603 2144.73,-305.55 r180 top value=0
R93 "CRCW06030000Z0EA" 0603 2145,-370 r180 top value=0
R94 "CRCW120616R5FKEA" 1206 2130,5210 r0 top value=16.5
R96 "CRCW060310K0JNEA" 0603 5589,5686.5 r270 top value=10k
R98 "RC1206FR-07820KL" 1206 4115,-480 r0 bottom value=820k
R99 "CRCW06030000Z0EA" 0603 1975,1548.97 r180 bottom value=0
R100 "CRCW06030000Z0EA" 0603 1975,4022 r180 bottom value=0
R101 "CRCW06030000Z0EA" 0603 1978,405 r180 bottom value=0
R102 "CRCW06030000Z0EA" 0603 1975,3393 r180 bottom value=0
R103 "CRCW06030000Z0EA" 0603 1975,2783.97 r180 bottom value=0
R105 "CRCW06030000Z0EA" 0603 1977,2158 r180 bottom value=0
R106 "CRCW0603160KFKEA" 0603 2284.45,-259.73 r0 top value=160k
R107 "CRCW06031K00FKEA" 0603 2238,-651.5 r90 top value=1.00k
R108 "RC1206FR-07820KL" 1206 3750,-480 r0 bottom value=820k
R109 "CRCW06031K00FKEA" 0603 3213,-547.5 r270 bottom value=1.00k
R110 "CRCW06030000Z0EA" 0603 2733.33,-350.68 r180 top value=0
R112 "CRCW060310K0JNEA" 0603 2605,1345 r90 top value=10k
R118 "PU5931FKMP70R004L" PU5931_146 5470,3300 r0 top value=0.004
R120 "PU5931FKMP70R004L" PU5931_146 5470,1495 r0 top value=0.004
R122 "RC1206FR-07820KL" 1206 3685,-660 r90 bottom value=820k
R125 "RC1206FR-07820KL" 1206 3630,-860 r0 bottom value=820k
R127 "RC1206FR-07820KL" 1206 3417.91,-860 r0 bottom value=820k
R128 "RC1206FR-07820KL" 1206 3210,-860 r0 bottom value=820k
R129 "RC1206FR-07820KL" 1206 3153,-710 r270 bottom value=820k
R139 "CRCW06031K00FKEA" 0603 1360,3225 r270 top value=1.00k
R140 "CRCW06031K00FKEA" 0603 1360,3845 r270 top value=1.00k
R141 "CRCW06031K00FKEA" 0603 1359,1990 r270 top value=1.00k
R142 "CRCW06031K00FKEA" 0603 1360,2606.97 r270 top value=1.00k
R143 "CRCW06031K00FKEA" 0603 1360,1371.97 r270 top value=1.00k
R144 "CRCW06031K00FKEA" 0603 1360,237 r270 top value=1.00k
TP1 "5000" Keystone5000 1161,-678 r90 top
TP2 "5000" Keystone5000 1161,-828 r90 top
TP3 "5000" Keystone5000 1254,-250 r90 top
TP4 "5000" Keystone5000 777,4110 r90 top
TP5 "5000" Keystone5000 1340,4660 r90 top
TP6 "5000" Keystone5000 1325,4375 r90 top
TP7 "5000" Keystone5000 2577,-474 r90 top
TP10 "5000" Keystone5000 1263,1022 r90 top
TP11 "5000" Keystone5000 1263,877 r90 top
TP12 "TESTPOINT" TP_VIA_060RND040 2890,3850 r90 top
TP13 "TESTPOINT" TP_VIA_060RND040 2890,3635 r90 top
TP14 "TESTPOINT" TP_VIA_060RND040 2890,2650 r90 top
TP15 "5000" Keystone5000 1263,-425 r90 top
TP16 "TESTPOINT" TP_VIA_060RND040 2890,2435 r90 top
TP17 "TESTPOINT" TP_VIA_060RND040 2890,1450 r90 top
TP18 "TESTPOINT" TP_VIA_060RND040 2890,1235 r90 top
TP19 "TESTPOINT" TP_VIA_060RND040 2890,850 r90 top
TP20 "TESTPOINT" TP_VIA_060RND040 2890,635 r90 top
TP21 "TESTPOINT" TP_VIA_060RND040 2890,2040 r90 top
TP22 "TESTPOINT" TP_VIA_060RND040 2890,1825 r90 top
TP23 "TESTPOINT" TP_VIA_060RND040 2890,3250 r90 top
TP24 "TESTPOINT" TP_VIA_060RND040 2890,3035 r90 top
TP25 "TESTPOINT" TP_VIA_060RND040 4040,160 r180 top
TP26 "TESTPOINT" TP_VIA_060RND040 4040,4384 r180 top
TP27 "TESTPOINT" TP_VIA_060RND040 4485,3606 r180 top
TP28 "TESTPOINT" TP_VIA_060RND040 4755,3450 r180 top
TP29 "5000" Keystone5000 5260,3560 r180 top
TP30 "TESTPOINT" TP_VIA_060RND040 2889,3554 r180 top
TP31 "5000" Keystone5000 5260,2548 r90 top
TP32 "5000" Keystone5000 5260,1760 r90 top
TP33 "TESTPOINT" TP_VIA_060RND040 3770,160 r180 top
TP34 "TESTPOINT" TP_VIA_060RND040 3770,4384 r180 top
TP35 "TESTPOINT" TP_VIA_060RND040 2983,3348 r90 top
TP36 "5000" Keystone5000 2428,-219 r270 top
TP37 "5000" Keystone5000 2410,-540 r90 top
U1 "UCC5310MCDWV" DWV0008A 1730,3850 r0 top
U2 "UCC5310MCDWV" DWV0008A 1730,3230 r0 top
U3 "TLV1117-33IDRJR" DRJ0008A 602,4125 r0 top
U4 "SN74LVC1G17DCKR" DCK0005A_N 799,2758 r0 top
U5 "UCC5310MCDWV" DWV0008A 1730,1376.97 r0 top
U6 "UCC5310MCDWV" DWV0008A 1730,242 r0 top
U7 "UCC5310MCDWV" DWV0008A 1730,2611.97 r0 top
U8 "UCC5310MCDWV" DWV0008A 1729,1995 r0 top
U9 "TLV521" DCK0005A_N 2280,-405 r180 top
U10 "UCC5320SCDWV" DWV0008A 1730,5150 r0 top
U12 "AMC1306E25DWVR" DWV0008A 1729.73,-763.55 r180 top
U13 "AMC1306E25DWVR" DWV0008A 1729.73,4501.58 r180 top
U14 "AMC1306E25DWVR" DWV0008A 1729.5,946 r180 top
U15 "AMC1306E25DWVR" DWV0008A 1729.73,-335.55 r180 top
U20 "LM3480IM3-5.0/NOPB" MF03A_N 2155,4315 r0 top
U22 "LM3480IM3-5.0/NOPB" MF03A_N 2174.77,765.55 r0 top
U23 "TLV70433DBVR" DBV0005A_N 2702.33,-632.68 r270 top
U24 "CM100TX-24S1" CM100TX-24S1 3901.89,2249.76 r270 bottom locked
XF1 "3566" Keystone_3566 3491.5,5722 r0 top value=5AG
XF2 "3566" Keystone_3566 4613.16,5722 r0 top value=5AG
ZZ1 "This Assembly Note is for PCB labels only" AssemblyNoteLabel -845.27,6629.45 r0 top
ZZ2 "These assemblies are ESD sensitive, ESD precautions shall be observed." AssemblyNote 509.73,9185.45 r0 top
ZZ3 "These assemblies must be clean and free from flux and all contaminants. Use of no clean flux is not acceptable." AssemblyNote 509.73,9100.45 r0 top
ZZ4 "These assemblies must comply with workmanship standards IPC-A-610 Class 2, unless otherwise specified." AssemblyNote 509.73,9025.45 r0 top

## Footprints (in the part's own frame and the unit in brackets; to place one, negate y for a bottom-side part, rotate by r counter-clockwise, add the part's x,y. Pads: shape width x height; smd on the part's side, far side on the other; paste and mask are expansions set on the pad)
0603 [mm] "0603 from SM-752 data"
  rect 1x0.95 smd: 1(-0.8,0) 2(0.8,0)
  silkscreen extent -1.52,-0.69 1.52,0.69, body extent -0.87,-0.47 0.87,0.47, height 1
0805_HV [mil] "0805 with 30mil clearance between pads"
  rect 50x63 smd: 1(-40,0) 2(40,0)
  silkscreen extent -74,-40 74,40, body extent -43,-29 43,29, height 57
1206 [mm] "1206 from SM-752 data"
  rect 1.3x1.85 smd: 1(-1.45,0) 2(1.45,0)
  silkscreen extent -2.4,-1.21 2.4,1.21, body extent -1.7,-0.9 1.7,0.9, height 1.35
1206L [mm] "1206 from SM-752 data"
  rect 1.1x1.75 smd: 1(-1.35,0) 2(1.35,0)
  silkscreen extent -0.4,-0.77 0.4,0.77, body extent -1.7,-0.9 1.7,0.9, height 1.35
1210_270 [mm] "1210"
  rect 1.3x2.7 smd: 1(-1.45,0) 2(1.45,0)
  silkscreen extent -2.32,-1.57 2.32,1.57, body extent -1.7,-1.35 1.7,1.35, height 2.7
1210_280 [mm] "SMD, 2-Leads, Body 3.6x2.8mm, Height 2.8mm"
  rect 1.1x2.2 smd: 1(-1.65,0) 2(1.65,0)
  silkscreen extent -0.84,-1.4 0.84,1.4, body extent -1.8,-1.4 1.8,1.4, height 2.8
Amp_DB25 [mil] "Amp 5747461-1"
  rect 75x75 hole 41: 1(-654,-193.5)
  round 75 hole 41: 2(-545,-193.5) 3(-436,-193.5) 4(-327,-193.5) 5(-218,-193.5) 6(-109,-193.5) 7(0,-193.5) 8(109,-193.5) 9(218,-193.5) 10(327,-193.5) 11(436,-193.5) 12(545,-193.5) 13(654,-193.5) 14(-599.5,-81.5) 15(-490.5,-81.5) 16(-381.5,-81.5) 17(-272.5,-81.5) 18(-163.5,-81.5) 19(-54.5,-81.5) 20(54.5,-81.5) 21(163.5,-81.5) 22(272.5,-81.5) 23(381.5,-81.5) 24(490.5,-81.5) 25(599.5,-81.5)
  round 200 hole 120: 26(-928,193.5) 27(928,193.5)
  silkscreen extent -1066,-298 1060,407, body extent -1042,-221 1048,751, height 455
AssemblyNote [mil] "Assembly Note"
AssemblyNoteLabel [mil] "Assembly Note for PCB Labels"
B32774_3150x1800x2750 [mm] "TH, 2-Leads, Body 31.5x18mm, Pin Spacing 27.5mm"
  round 1.6 hole 1.1: 1(-13.75,0) 2(13.75,0)
  silkscreen extent -15.75,-9 15.75,9, body extent -15.75,-9 15.75,9, height 27.5
CM100TX-24S1 [mm] "TH, 35-Leads, Body 121.7x62mm"
  rrect50% 2.2x2.2 hole 1.7: 1(-40.01,28.975)
  round 2.2 hole 1.7: 2(-36.19,28.975) 3(-24.77,28.975) 4(-20.95,28.975) 5(-9.53,28.975) 6(-5.71,28.975) 7(5.71,28.975) 8(9.53,28.975) 9(20.95,28.975) 10(24.77,28.975) 11(36.19,28.975) 12(40.01,28.975) 13(59.055,13.34) 14(59.055,9.53) 15(59.055,5.71) 16(59.055,-5.71) 17(59.055,-9.52) 18(59.055,-13.34) 19(41.91,-28.975) 20(38.1,-28.975) 21(22.86,-28.975) 22(19.05,-28.975) 23(15.24,-28.975) 24(0,-28.975) 25(-3.81,-28.975) 26(-7.62,-28.975) 27(-22.86,-28.975) 28(-26.67,-28.975) 29(-30.48,-28.975) 30(-59.055,-13.34) 31(-59.055,-9.53) 32(-59.055,-5.71) 33(-59.055,5.71) 34(-59.055,9.53) 35(-59.055,13.34)
  round 0 hole 2.6 unplated mask+1.473: MH1(-47.25,28.75) MH2(47.25,28.75) MH3(-47.25,-28.75) MH4(47.25,-28.75)
  silkscreen extent -60.85,-31 60.85,31.9, body extent -60.85,-31 60.85,31, height 17
DBV0005A_N [mm] "SOT23, 5-Leads, Body 2.9x1.6mm, Pitch 0.95mm, Lead Span 2.8mm, IPC Medium Density"
  rrect17% 1x0.6 smd: 1(-1.375,0.95) 2(-1.375,0) 3(-1.375,-0.95) 4(1.375,-0.95) 5(1.375,0.95)
  silkscreen extent -1.63,-1.55 0.38,1.55, body extent -1.42,-1.46 1.42,1.46, height 1.09
DCK0005A_N [mm] "SOT353, 5-Leads, Body 2x1.3mm, Pitch 0.65mm, Lead Span 2.1mm, IPC Medium Density"
  rrect25% 0.85x0.4 smd: 1(-1.125,0.65) 2(-1.125,0) 3(-1.125,-0.65) 4(1.125,-0.65) 5(1.125,0.65)
  silkscreen extent -1.48,-1.02 0.55,1.1, body extent -1.14,-1 1.14,1, height 0.95
DRJ0008A [mm] "SON, 8-Leads, Body 4x4mm, Pitch 0.8mm, Thermal Pad 3x2.2mm, TI Recommended"
  oval 0.7x0.3 smd: 1(-1.9,1.2) 2(-1.9,0.4) 3(-1.9,-0.4) 4(-1.9,-1.2) 5(1.9,-1.2) 6(1.9,-0.4) 7(1.9,0.4) 8(1.9,1.2)
  rect 2.2x3 smd paste-1.1: 9(0,0)
  silkscreen extent -2.2,-2.2 2.2,2.2, body extent -2.05,-2.05 2.05,2.05, height 0.81
DWV0008A [mm] "SOIC, 8-Leads, Body 5.95x7.6mm (max), Pitch 1.27mm"
  rrect17% 1.8x0.6 smd: 1(-5.45,1.905) 2(-5.45,0.635) 3(-5.45,-0.635) 4(-5.45,-1.905) 5(5.45,-1.905) 6(5.45,-0.635) 7(5.45,0.635) 8(5.45,1.905)
  silkscreen extent -6.25,-2.95 2.98,2.95, body extent -5.77,-2.92 5.77,2.93, height 2.67
ESD_Overlay_Medium [mil]
  silkscreen extent -127,-109 125,110
FCC_disclaimer [mil]
Fiducial10-20 [mm]
  round 1 smd mask+0.5: 1(0,0)
  Top Layer keep-out circle w1.178: c0,0 r0.5
IEC_HighVoltage_medium [mil]
  silkscreen extent -217,-176 217,200
IEC_HotSurface_Medium [mil]
  silkscreen extent -217,-188 217,188
Keystone5000 [mil] "For Keystone 500x miniature loop terminals"
  round 80 hole 40: 1(0,0)
  silkscreen extent -58,-58 58,58, body extent -49,-49 49,49, height 182
Keystone_1902C [mil] "Hex Standoff, 4-40 threaded, nylon"
  round 1 on Mech4: 0(0,0)
  body extent -145,-126 146,126, height 501
Keystone_3566 [mm] "Keyston"
  round 2.85 hole 2.25: 1(-5.245,0) 2(5.245,0)
  silkscreen extent -5.61,-6.22 5.61,6.22, body extent -5.63,-6.14 5.63,6.14, height 18.98
Label_650x200 [mil] "Thermal Transfer Label"
  round 1 on Mech13: 0(0,0)
  silkscreen extent -325,-100 325,100, body extent -325,-100 325,100, height 1
MF03A_N [mm] "SOT23, 3-Leads, Body 2.9x1.3mm, Pitch 0.95mm, Lead Span 2.4mm, IPC Medium Density"
  rect 1.3x0.6 smd: 1(-1.05,0.95) 2(-1.05,-0.95) 3(1.05,0)
  silkscreen extent -1.17,-1.5 0.7,1.92, body extent -0.7,-1.5 0.7,1.5, height 1.12
MH3.2_H5_W6_KO8_STARHEAD [mil]
  round 20 / inner round 142 / far side round 20 hole 128 unplated mask+65: 1(0,0)
  Keep-Out Layer region: 160.49,0 158.52,25.11 152.64,49.6 143,72.86 129.84,94.34 113.49,113.49 94.34,129.84 72.86,143 49.6,152.64 25.11,158.52 0,160.49 -25.11,158.52 -49.6,152.64 -72.86,143 -94.34,129.84 -113.49,113.49 -129.84,94.34 -143,72.86 -152.64,49.6 -158.52,25.11 -160.49,0 -158.52,-25.11 -152.64,-49.6 -143,-72.86 -129.84,-94.34 -113.49,-113.49 -94.34,-129.84 -72.86,-143 -49.6,-152.64 -25.11,-158.52 0,-160.49 25.11,-158.52 49.6,-152.64 72.86,-143 94.34,-129.84 113.49,-113.49 129.84,-94.34 143,-72.86 152.64,-49.6 158.52,-25.11
  silkscreen extent -120,-120 120,120
MicroSMP [mm] "SMD, 2-Leads, Body 2.2x1.3mm"
  rect 2x1.1 smd: 1(-0.65,0)
  rect 0.8x0.8 smd: 2(1.25,0)
  silkscreen extent -2.2,-1 1.6,1, body extent -1.15,-0.7 1.15,0.7, height 0.75
Mill-Max_800-10-003-10-001000 [mm] "Mill-Max"
  rect 1.5x1.5 hole 0.85: 1(-2.54,0)
  round 1.5 hole 0.85: 2(0,0) 3(2.54,0)
  silkscreen extent -3.81,-1.27 3.81,1.78, body extent -3.81,-1.27 3.81,1.27, height 8.13
Pb-Free_Overlay_Small [mil]
  silkscreen extent -46,-46 46,46
Phoenix_1902547 [mm] "TH, 2-Leads, Body 19.04x16mm, Pitch 9.52mm"
  rect 1.8x1.8 hole 1.3: 1(-4.76,3.1)
  round 1.8 hole 1.3: 2(4.76,3.1)
  silkscreen extent -10,-8 10.09,8, body extent -9.52,-8 10.09,8, height 22
Phoenix_1904150 [mm] "TH, 3-Leads, Body 28.56x16mm, Pitch 9.52mm"
  rect 1.8x1.8 hole 1.3: 1(-9.52,3.1)
  round 1.8 hole 1.3: 2(0,3.1) 3(9.52,3.1)
  silkscreen extent -14.8,-8 14.85,8, body extent -14.28,-8 14.85,8, height 22
PU5931_146 [mm] "SMD, 2-Leads, Body 15x7.75mm"
  rect 5.2x8.75 smd: 1(-5.4,0) 2(5.4,0)
  silkscreen extent -2.4,-3.88 2.4,3.87, body extent -7.5,-3.87 7.5,3.88, height 1.46
SMA [mm] "Molded Diode, 2-Leads, Body 4.3x2.6mm, IPC Medium Density, based on OnSemi component dimensions and land pattern"
  rect 2x2 smd: 1(-2,0) 2(2,0)
  silkscreen extent -3.66,-1.57 2.79,1.57, body extent -2.6,-1.3 2.6,1.3, height 2.42
SMB [mil] "Molded Diode, 2-Leads, Body 5.4x3.6mm, IPC Medium Density, based on OnSemi component dimensions"
  rect 85x107.99 smd: 1(-87.01,0) 2(87.01,0)
  silkscreen extent -155,-82 125,82, body extent -106,-71 106,71, height 91
SOD-123 [mm] "On Semi recommended land pattern"
  rect 0.915x1.22 smd: 1(-1.637,0) 2(1.637,0)
  silkscreen extent -2.74,-1.17 2.03,1.17, body extent -1.93,-0.9 1.93,0.9, height 1.35
TEC_282834-2 [mm] "TEC"
  rect 1.6x1.6 hole 1.1: 1(-1.27,0)
  round 1.6 hole 1.1: 2(1.27,0)
  silkscreen extent -3.66,-3.4 2.9,3.4, body extent -2.77,-3.25 2.77,3.25, height 10.01
TO-247 [mil] "Standard TO-247"
  rect 95x95 hole 62: 1(-215,0)
  round 95 / inner round 74.8 / far side round 96 hole 62: 2(0,0) 3(215,0)
  silkscreen extent -318,-124 318,81, body extent -318,-124 318,81, height 1007
TO-247-2 [mm] "TH, 2-Leads, Body 15.75x4.95mm, Pin Spacing 10.16mm"
  round 2.6 hole 2.1: 1(-5.08,-0.21) 2(5.08,-0.21)
  silkscreen extent -8.01,-2.61 8.01,2.61, body extent -8.01,-2.61 8,2.6, height 23.77
TP_VIA_060RND040 [mil] "TP_VIA_060RND040"
  round 60 hole 40: 1(0,0)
